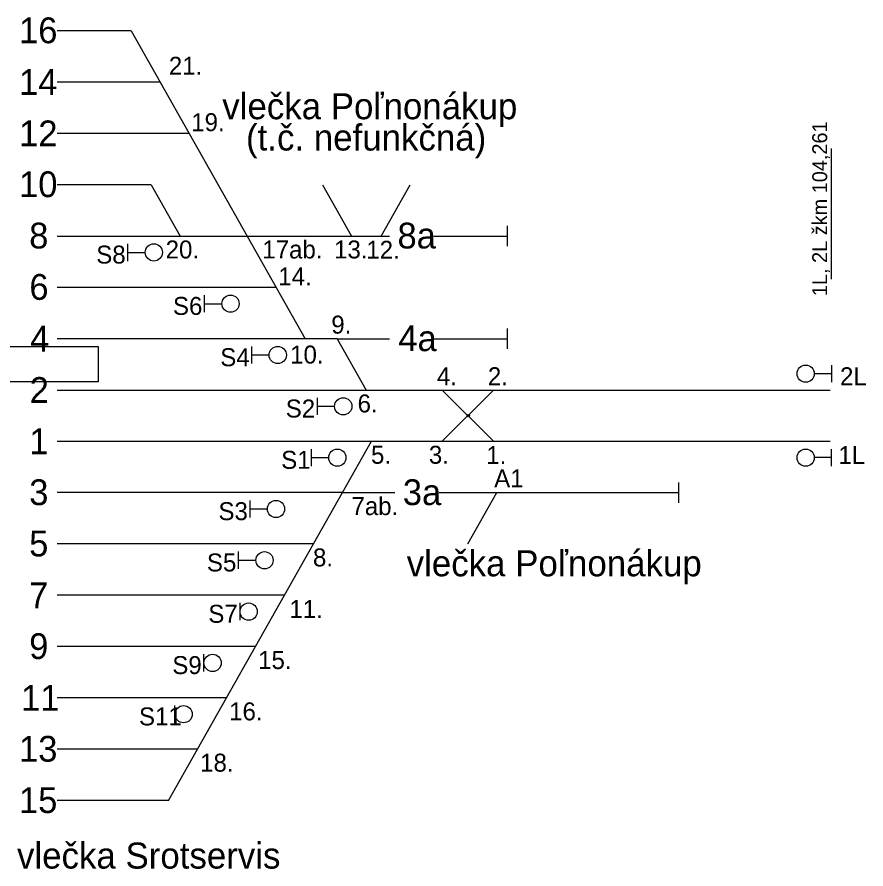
# Model space of a CAD drawing. Extents: x -119 to 851, y -238 to 59.
# Drawn here: x 437.12 to 470.17, y -65.1 to -31.92 of the extents above; entities that cross this region are included whole.
import ezdxf

# ---------------------------------------------------------------- set-up
doc = ezdxf.new("R2010")
doc.units = 0
for name, color, linetype in [('Level 2', 7, 'Continuous'), ('nastupistia', 7, 'Continuous'), ('netlač', 7, 'Continuous'), ('popisky navestidla', 7, 'Continuous'), ('PU_navestidla', 7, 'Continuous'), ('PU_oznacenie navestidiel', 7, 'Continuous'), ('PU_stan_kolaje', 7, 'Continuous'), ('PU_vlecky', 7, 'Continuous'), ('schema_km0-1_0-2', 7, 'Continuous')]:
    doc.layers.add(name, color=color, linetype=linetype)

msp = doc.modelspace()

# ---------------------------------------------------------------- linework, layer by layer
at = {"layer": 'Level 2'}
for p, q in [((456.219, -40.85), (456.219, -40.051)), ((456.219, -44.85), (456.219, -44.05)), ((438.689, -46.448), (445.588, -46.448)), ((445.588, -46.448), (468.786, -46.448)), ((438.689, -48.447), (446.588, -48.447)), ((446.588, -48.447), (464.886, -48.447)), ((464.886, -48.447), (468.786, -48.447)), ((462.885, -50.845), (462.885, -50.046))]:
    msp.add_line(p, q, dxfattribs=at)
msp.add_lwpolyline([(438.689, -40.453), (446.078, -40.453)], dxfattribs=at)
at = {"layer": 'nastupistia'}
msp.add_lwpolyline([(440.274, -46.136), (419, -46.136), (419, -44.751), (440.274, -44.751)], close=True, dxfattribs=at)
at = {"layer": 'netlač'}
for p, q in [((441.558, -32.459), (438.689, -32.459)), ((442.688, -34.457), (438.689, -34.457)), ((443.818, -36.456), (438.689, -36.456)), ((442.347, -38.454), (438.689, -38.454)), ((446.077, -40.451), (451.626, -40.451)), ((453.35, -40.451), (456.219, -40.451)), ((447.208, -42.451), (438.689, -42.451)), ((449.585, -44.45), (438.689, -44.45)), ((449.585, -44.45), (451.626, -44.45)), ((453.35, -44.45), (456.219, -44.45)), ((449.793, -50.446), (438.689, -50.446)), ((449.793, -50.446), (451.835, -50.446)), ((453.558, -50.446), (462.885, -50.446)), ((448.663, -52.444), (438.689, -52.444)), ((447.533, -54.443), (438.689, -54.443)), ((446.403, -56.441), (438.689, -56.441)), ((445.273, -58.44), (438.689, -58.44)), ((444.143, -60.438), (438.689, -60.438)), ((443.013, -62.436), (438.689, -62.436))]:
    msp.add_line(p, q, dxfattribs=at)
at = {"layer": 'popisky navestidla'}
msp.add_line((468.834, -42.136), (468.834, -37.045), dxfattribs=at)
at = {"layer": 'PU_navestidla'}
for p, q in [((441.439, -41.425), (441.439, -40.753)), ((441.439, -41.087), (442.111, -41.087)), ((444.425, -43.423), (444.425, -42.751)), ((444.425, -43.086), (445.097, -43.086)), ((446.265, -45.422), (446.265, -44.75)), ((446.265, -45.084), (446.937, -45.084)), ((468.834, -45.476), (468.834, -46.148)), ((468.834, -45.814), (468.162, -45.814)), ((448.813, -47.42), (448.813, -46.748)), ((448.813, -47.083), (449.485, -47.083)), ((448.583, -49.419), (448.583, -48.747)), ((468.834, -49.419), (468.834, -48.747)), ((448.583, -49.082), (449.255, -49.082)), ((468.834, -49.082), (468.162, -49.082)), ((446.196, -51.418), (446.196, -50.746)), ((446.196, -51.08), (446.868, -51.08)), ((445.749, -53.416), (445.749, -52.744)), ((445.749, -53.079), (446.421, -53.079)), ((445.804, -55.415), (445.804, -54.743)), ((444.399, -57.412), (444.399, -56.74)), ((443.269, -59.41), (443.269, -58.738))]:
    msp.add_line(p, q, dxfattribs=at)
for centre in [(442.447, -41.089), (445.433, -43.087), (447.273, -45.086), (467.826, -45.812), (449.821, -47.084), (449.591, -49.083), (467.826, -49.083), (447.204, -51.082), (446.757, -53.08), (446.14, -55.079), (444.735, -57.076), (443.605, -59.074)]:
    msp.add_circle(centre, 0.336, dxfattribs=at)
at = {"layer": 'PU_stan_kolaje'}
for points in [[(441.558, -32.459), (442.688, -34.457)], [(442.688, -34.457), (443.818, -36.456)], [(443.818, -36.456), (444.948, -38.454)], [(442.347, -38.454), (443.477, -40.453)], [(444.948, -38.454), (446.078, -40.453)], [(449.015, -38.452), (450.144, -40.451)], [(451.295, -40.451), (452.424, -38.452)], [(446.078, -40.453), (447.208, -42.451)], [(447.208, -42.451), (448.338, -44.45)], [(449.585, -44.45), (450.715, -46.448)], [(453.674, -46.448), (455.673, -48.447)], [(455.673, -46.448), (453.674, -48.447)], [(449.793, -50.446), (450.923, -48.447)], [(448.663, -52.444), (449.793, -50.446)], [(454.675, -52.444), (455.805, -50.446)], [(447.533, -54.443), (448.663, -52.444)], [(446.403, -56.441), (447.533, -54.443)], [(445.273, -58.44), (446.403, -56.441)], [(444.143, -60.438), (445.273, -58.44)], [(443.013, -62.436), (444.143, -60.438)]]:
    msp.add_lwpolyline(points, dxfattribs=at)
at = {"layer": 'schema_km0-1_0-2'}
msp.add_circle((454.691, -47.448), 0.0502, dxfattribs=at)

# ---------------------------------------------------------------- texts
at = {"layer": 'popisky navestidla'}
msp.add_text('1L, 2L žkm 104,261', height=0.57931, rotation=90, dxfattribs=at).set_placement((468.663, -42.792))
at = {"layer": 'PU_oznacenie navestidiel'}
for s, p in [('21.', (443.032, -34.171)), ('19.', (443.903, -36.368)), ('20.', (442.907, -41.325)), ('17ab.', (446.671, -41.325)), ('13.', (449.466, -41.325)), ('12.', (450.72, -41.337)), ('S8', (440.205, -41.524)), ('14.', (447.293, -42.375)), ('S6', (443.192, -43.523)), ('9.', (449.357, -44.252)), ('10.', (447.755, -45.418)), ('S4', (445.033, -45.521)), ('4.', (453.468, -46.262)), ('2.', (455.454, -46.262)), ('2L', (469.164, -46.262)), ('6.', (450.38, -47.322)), ('S2', (447.583, -47.519)), ('5.', (450.903, -49.321)), ('3.', (453.156, -49.321)), ('1.', (455.391, -49.333)), ('1L', (469.101, -49.333)), ('S1', (447.406, -49.518)), ('A1', (455.698, -50.239)), ('7ab.', (450.142, -51.32)), ('S3', (444.963, -51.517)), ('8.', (448.643, -53.318)), ('S5', (444.514, -53.515)), ('11.', (447.723, -55.329)), ('S7', (444.568, -55.514)), ('15.', (446.509, -57.315)), ('S9', (443.166, -57.512)), ('16.', (445.379, -59.314)), ('S11', (441.869, -59.511)), ('18.', (444.249, -61.312))]:
    msp.add_text(s, height=0.7, dxfattribs=at).set_placement(p)
at = {"layer": 'PU_stan_kolaje'}
for s, height, p in [('16', 1.0044, (437.199, -32.942)), ('14', 1.0044, (437.2, -34.957)), ('12', 1.0044, (437.202, -36.956)), ('10', 1.0044, (437.2, -38.937)), ('8', 1.004, (437.594, -40.936)), ('8a', 1.0044, (451.934, -40.936)), ('6', 1.004, (437.601, -42.936)), ('4', 1.004, (437.629, -44.952)), ('4a', 1.0044, (451.967, -44.935)), ('2', 1.004, (437.613, -46.95)), ('1', 1.004, (437.598, -48.949)), ('3', 1.004, (437.596, -50.931)), ('3a', 1.0044, (452.142, -50.931)), ('5', 1.004, (437.593, -52.929)), ('7', 1.004, (437.589, -54.945)), ('9', 1.004, (437.594, -56.926)), ('11', 1.0044, (437.278, -58.942)), ('13', 1.0044, (437.199, -60.923)), ('15', 1.0044, (437.196, -62.922))]:
    msp.add_text(s, height=height, dxfattribs=at).set_placement(p)
at = {"layer": 'PU_vlecky'}
for s, p in [('vlečka Poľnonákup', (445.112, -35.903)), ('(t.č. nefunkčná)', (446.036, -37.121)), ('vlečka Poľnonákup', (452.292, -53.704)), ('vlečka Srotservis', (437.119, -65.087))]:
    msp.add_text(s, height=1.015, dxfattribs=at).set_placement(p)

doc.saveas('drawing.dxf')
